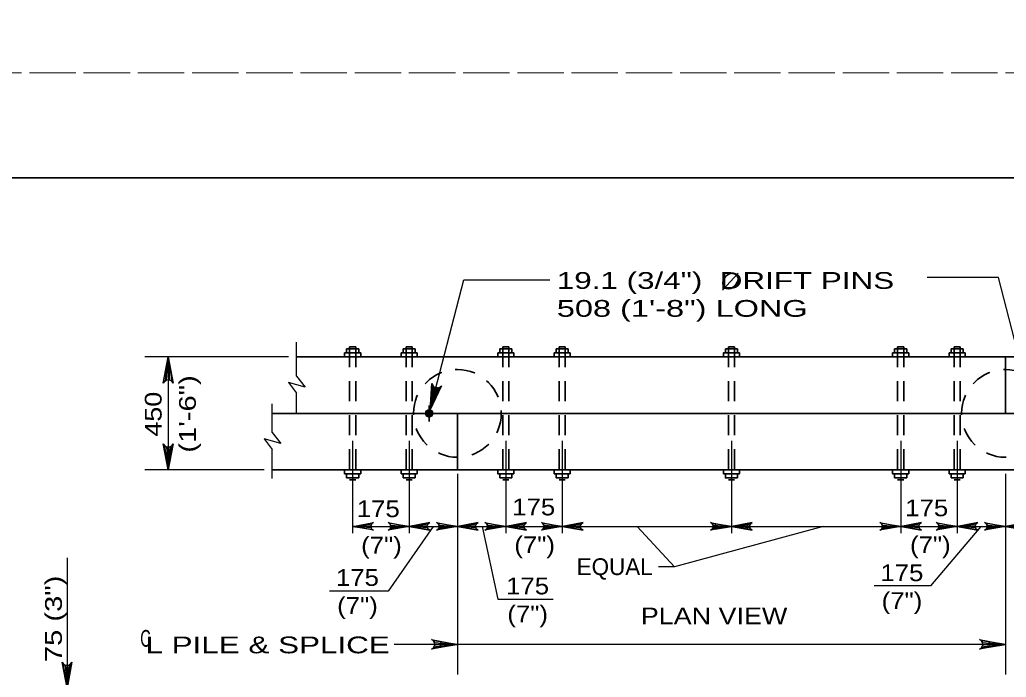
# Model space of a CAD drawing. Extents: x -6.4 to 73.1, y -66 to 0.
# Drawn here: x 22.39 to 29.45, y -26.33 to -21.62 of the extents above; entities that cross this region are included whole.
import ezdxf
from ezdxf.enums import TextEntityAlignment as Align

# ---------------------------------------------------------------- set-up
doc = ezdxf.new("R2010")
doc.units = 0
doc.header["$LTSCALE"] = 0.048
doc.linetypes.add('LONG_DASHED', pattern=[7.5, 6, -1.5])
doc.linetypes.add('MEDIUM_DASHED', pattern=[4.5, 3, -1.5])
for name, color, linetype, lineweight in [('1', 7, 'Continuous', 13), ('4', 7, 'Continuous', 25), ('5', 7, 'Continuous', 25), ('52', 7, 'Continuous', 25), ('63', 7, 'LONG_DASHED', 13)]:
    doc.layers.add(name, color=color, linetype=linetype, lineweight=lineweight)

msp = doc.modelspace()

# ---------------------------------------------------------------- hatches: boundary and pattern name
at = {"layer": '5'}
for points in [[(23.43483, -24.14433), (23.47175, -24.14433), (23.45325, -24.03358)], [(23.43483, -24.73025), (23.47175, -24.73025), (23.45325, -24.841)], [(27.36842, -25.22717), (27.36842, -25.26558), (27.48375, -25.24633)], [(27.59908, -25.26558), (27.59908, -25.22717), (27.48375, -25.24633)], [(25.40275, -26.07175), (25.40275, -26.11025), (25.51817, -26.091)], [(29.32925, -26.07175), (29.32925, -26.11025), (29.44458, -26.091)]]:
    msp.add_hatch(color=256, dxfattribs=at).paths.add_polyline_path(points)

# ---------------------------------------------------------------- linework, layer by layer
at = {"layer": '1', "lineweight": 35}
msp.add_lwpolyline([(1.75, -43.25), (33.25, -43.25), (33.25, -22.75), (1.75, -22.75)], close=True, dxfattribs=at)
at = {"layer": '4'}
for p, q in [((24.371, -24.17142), (24.371, -23.92742)), ((24.371, -24.43733), (24.371, -24.29217)), ((24.1965, -24.57508), (24.1965, -24.37)), ((24.14067, -24.61925), (24.1965, -24.69583)), ((24.25992, -24.653), (24.14067, -24.61925)), ((24.1965, -24.57508), (24.25992, -24.653)), ((24.1965, -24.90425), (24.1965, -24.69583))]:
    msp.add_line(p, q, dxfattribs=at)
at = {"layer": '4', "lineweight": 35}
for p, q in [((24.73, -24.00475), (24.73, -23.97592)), ((24.73, -23.97592), (24.8165, -23.97592)), ((24.75158, -23.9615), (24.79483, -23.9615)), ((24.8165, -24.00475), (24.8165, -23.97592)), ((25.13367, -24.00475), (25.13367, -23.97592)), ((25.13367, -23.97592), (25.22017, -23.97592)), ((25.15533, -23.9615), (25.19858, -23.9615)), ((25.22017, -24.00475), (25.22017, -23.97592)), ((25.84733, -23.9615), (25.89058, -23.9615)), ((25.91225, -24.00475), (25.91225, -23.97592)), ((26.22942, -23.97592), (26.31592, -23.97592)), ((26.22942, -24.00475), (26.22942, -23.97592)), ((26.25108, -23.9615), (26.29433, -23.9615)), ((26.31592, -24.00475), (26.31592, -23.97592)), ((27.4405, -24.00475), (27.4405, -23.97592)), ((27.4405, -23.97592), (27.527, -23.97592)), ((27.46217, -23.9615), (27.50542, -23.9615)), ((27.527, -24.00475), (27.527, -23.97592)), ((28.65158, -23.97592), (28.73808, -23.97592)), ((28.65158, -24.00475), (28.65158, -23.97592)), ((28.67325, -23.9615), (28.7165, -23.9615)), ((28.73808, -24.00475), (28.73808, -23.97592)), ((29.05525, -24.00475), (29.05525, -23.97592)), ((29.05525, -23.97592), (29.14175, -23.97592)), ((29.07692, -23.9615), (29.12017, -23.9615)), ((29.14175, -24.00475), (29.14175, -23.97592)), ((30.59658, -24.03358), (24.371, -24.03358)), ((24.71558, -24.03358), (24.71558, -24.00475)), ((24.71558, -24.00475), (24.83092, -24.00475)), ((24.83092, -24.03358), (24.83092, -24.00475)), ((25.11925, -24.03358), (25.11925, -24.00475)), ((25.11925, -24.00475), (25.23458, -24.00475)), ((25.23458, -24.03358), (25.23458, -24.00475)), ((25.81133, -24.03358), (25.81133, -24.00475)), ((25.81133, -24.00475), (25.92667, -24.00475)), ((25.92667, -24.03358), (25.92667, -24.00475)), ((26.215, -24.00475), (26.33033, -24.00475)), ((26.215, -24.03358), (26.215, -24.00475)), ((26.33033, -24.03358), (26.33033, -24.00475)), ((27.54142, -24.03358), (27.54142, -24.00475)), ((28.63717, -24.00475), (28.7525, -24.00475)), ((28.63717, -24.03358), (28.63717, -24.00475)), ((28.7525, -24.03358), (28.7525, -24.00475)), ((29.04083, -24.03358), (29.04083, -24.00475)), ((29.04083, -24.00475), (29.15625, -24.00475)), ((29.15625, -24.03358), (29.15625, -24.00475)), ((29.44458, -24.03358), (29.44458, -24.43733)), ((25.32108, -24.37967), (25.32108, -24.495)), ((30.771, -24.43733), (24.1965, -24.43733)), ((25.26342, -24.43733), (25.37875, -24.43733)), ((25.52292, -24.43733), (25.52292, -24.841)), ((30.771, -24.841), (24.1965, -24.841)), ((24.71558, -24.841), (24.71558, -24.86983)), ((24.83092, -24.841), (24.83092, -24.86983)), ((25.11925, -24.841), (25.11925, -24.86983)), ((25.23458, -24.841), (25.23458, -24.86983)), ((25.92667, -24.841), (25.92667, -24.86983)), ((26.215, -24.841), (26.215, -24.86983)), ((26.33033, -24.841), (26.33033, -24.86983)), ((27.42608, -24.841), (27.42608, -24.86983)), ((27.54142, -24.841), (27.54142, -24.86983)), ((28.63717, -24.841), (28.63717, -24.86983)), ((28.7525, -24.841), (28.7525, -24.86983)), ((29.04083, -24.841), (29.04083, -24.86983)), ((29.15625, -24.841), (29.15625, -24.86983)), ((24.71558, -24.86983), (24.83092, -24.86983)), ((24.73, -24.86983), (24.73, -24.89867)), ((24.73, -24.89867), (24.8165, -24.89867)), ((24.75158, -24.91308), (24.79483, -24.91308)), ((24.8165, -24.86983), (24.8165, -24.89867)), ((25.11925, -24.86983), (25.23458, -24.86983)), ((25.13367, -24.86983), (25.13367, -24.89867)), ((25.13367, -24.89867), (25.22017, -24.89867)), ((25.15533, -24.91308), (25.19858, -24.91308)), ((25.22017, -24.86983), (25.22017, -24.89867)), ((25.82575, -24.86983), (25.82575, -24.89867)), ((25.82575, -24.89867), (25.91225, -24.89867)), ((25.84733, -24.91308), (25.89058, -24.91308)), ((25.91225, -24.86983), (25.91225, -24.89867)), ((26.215, -24.86983), (26.33033, -24.86983)), ((26.22942, -24.86983), (26.22942, -24.89867)), ((26.22942, -24.89867), (26.31592, -24.89867)), ((26.25108, -24.91308), (26.29433, -24.91308)), ((26.31592, -24.86983), (26.31592, -24.89867)), ((27.42608, -24.86983), (27.54142, -24.86983)), ((27.46217, -24.91308), (27.50542, -24.91308)), ((27.527, -24.86983), (27.527, -24.89867)), ((28.63717, -24.86983), (28.7525, -24.86983)), ((28.65158, -24.86983), (28.65158, -24.89867)), ((28.65158, -24.89867), (28.73808, -24.89867)), ((28.67325, -24.91308), (28.7165, -24.91308)), ((28.73808, -24.86983), (28.73808, -24.89867)), ((29.04083, -24.86983), (29.15625, -24.86983)), ((29.05525, -24.86983), (29.05525, -24.89867)), ((29.05525, -24.89867), (29.14175, -24.89867)), ((29.07692, -24.91308), (29.12017, -24.91308)), ((29.14175, -24.86983), (29.14175, -24.89867))]:
    msp.add_line(p, q, dxfattribs=at)
at = {"layer": '4', "linetype": 'MEDIUM_DASHED', "lineweight": 35}
for p, q in [((24.75158, -23.9615), (24.75158, -24.91308)), ((24.79483, -23.9615), (24.79483, -24.91308)), ((25.15533, -23.9615), (25.15533, -24.91308)), ((25.19858, -23.9615), (25.19858, -24.91308)), ((25.84733, -23.9615), (25.84733, -24.91308)), ((25.89058, -23.9615), (25.89058, -24.91308)), ((26.25108, -23.9615), (26.25108, -24.91308)), ((26.29433, -23.9615), (26.29433, -24.91308)), ((27.46217, -23.9615), (27.46217, -24.91308)), ((27.50542, -23.9615), (27.50542, -24.91308)), ((28.67325, -23.9615), (28.67325, -24.91308)), ((28.7165, -23.9615), (28.7165, -24.91308)), ((29.07692, -23.9615), (29.07692, -24.91308)), ((29.12017, -23.9615), (29.12017, -24.91308))]:
    msp.add_line(p, q, dxfattribs=at)
at = {"layer": '4', "lineweight": 35}
for points in [[(25.82575, -24.00475), (25.82575, -23.97592), (25.91225, -23.97592)], [(27.42608, -24.03358), (27.42608, -24.00475), (27.54142, -24.00475)], [(25.81133, -24.841), (25.81133, -24.86983), (25.92667, -24.86983)], [(27.4405, -24.86983), (27.4405, -24.89867), (27.527, -24.89867)]]:
    msp.add_lwpolyline(points, dxfattribs=at)
at = {"layer": '4'}
msp.add_lwpolyline([(24.371, -24.17142), (24.43433, -24.24933), (24.31508, -24.21558), (24.371, -24.29217)], dxfattribs=at)
at = {"layer": '4', "linetype": 'MEDIUM_DASHED', "lineweight": 35}
for centre in [(25.52289, -24.4373), (29.44452, -24.43733)]:
    msp.add_circle(centre, 0.31393, dxfattribs=at)
at = {"layer": '5', "lineweight": 35}
msp.add_line((27.419, -23.55508), (27.531, -23.4325), dxfattribs=at)
at = {"layer": '5'}
for p, q in [((24.31333, -24.03358), (23.28717, -24.03358)), ((23.45325, -24.03358), (23.45325, -24.841)), ((24.77325, -24.63433), (24.77325, -25.29592)), ((25.17692, -24.63433), (25.17692, -25.29592)), ((25.869, -24.63433), (25.869, -25.29592)), ((26.27267, -24.63433), (26.27267, -25.29592)), ((27.48375, -24.63433), (27.48375, -25.29592)), ((28.69483, -24.63433), (28.69483, -25.29592)), ((29.0985, -24.63433), (29.0985, -25.29592)), ((24.13883, -24.841), (23.28717, -24.841)), ((25.52292, -24.86983), (25.52292, -26.30625)), ((29.44458, -24.86983), (29.44458, -26.30625)), ((24.77325, -25.24633), (27.48375, -25.24633)), ((26.81008, -25.24633), (27.07575, -25.53483)), ((27.48375, -25.24633), (30.19425, -25.24633)), ((22.7295, -25.47083), (22.7295, -26.57733)), ((29.44458, -26.091), (25.071, -26.091))]:
    msp.add_line(p, q, dxfattribs=at)
for points in [[(25.32767, -24.4115), (25.56917, -23.48108), (26.18492, -23.48108)], [(29.64075, -24.41575), (29.39475, -23.46383), (28.88358, -23.46383)], [(23.45325, -24.03358), (23.48817, -24.22), (23.47825, -24.20567), (23.46575, -24.19825), (23.45325, -24.19608), (23.44075, -24.19825), (23.42825, -24.20567), (23.41833, -24.22), (23.45325, -24.03358), (23.42825, -24.20567), (23.44075, -24.19825), (23.45325, -24.03358), (23.45325, -24.19608), (23.46575, -24.19825), (23.45325, -24.03358), (23.47825, -24.20567)], [(25.32767, -24.4115), (25.34067, -24.22225), (25.34367, -24.2305), (25.34667, -24.23867), (25.35183, -24.24383), (25.35692, -24.249), (25.36267, -24.25158), (25.3685, -24.25417), (25.37483, -24.25475), (25.38108, -24.25525), (25.38808, -24.25325), (25.39508, -24.25125), (25.40167, -24.2455), (25.40833, -24.23983), (25.32767, -24.4115), (25.40167, -24.2455), (25.39508, -24.25125), (25.32767, -24.4115), (25.38808, -24.25325), (25.38108, -24.25525), (25.32767, -24.4115), (25.37483, -24.25475), (25.3685, -24.25417), (25.32767, -24.4115), (25.36267, -24.25158), (25.35692, -24.249), (25.32767, -24.4115), (25.35183, -24.24383), (25.34667, -24.23867), (25.32767, -24.4115), (25.34367, -24.2305)], [(23.45325, -24.841), (23.41833, -24.65458), (23.42825, -24.66892), (23.44075, -24.67633), (23.45325, -24.6785), (23.46575, -24.67633), (23.47825, -24.66892), (23.48817, -24.65458), (23.45325, -24.841), (23.47825, -24.66892), (23.46575, -24.67633), (23.45325, -24.841), (23.45325, -24.6785), (23.44075, -24.67633), (23.45325, -24.841), (23.42825, -24.66892)], [(24.77325, -25.24633), (24.92242, -25.21833), (24.91092, -25.22633), (24.905, -25.23633), (24.90325, -25.24633), (24.905, -25.25633), (24.91092, -25.26633), (24.92242, -25.27433), (24.77325, -25.24633), (24.91092, -25.26633), (24.905, -25.25633), (24.77325, -25.24633), (24.90325, -25.24633), (24.905, -25.23633), (24.77325, -25.24633), (24.91092, -25.22633)], [(25.17692, -25.24633), (25.02775, -25.27433), (25.03925, -25.26633), (25.04517, -25.25633), (25.04692, -25.24633), (25.04517, -25.23633), (25.03925, -25.22633), (25.02775, -25.21833), (25.17692, -25.24633), (25.03925, -25.22633), (25.04517, -25.23633), (25.17692, -25.24633), (25.04692, -25.24633), (25.04517, -25.25633), (25.17692, -25.24633), (25.03925, -25.26633)], [(25.17692, -25.24633), (25.32608, -25.27433), (25.31458, -25.26633), (25.30867, -25.25633), (25.30692, -25.24633), (25.30867, -25.23633), (25.31458, -25.22633), (25.32608, -25.21833), (25.17692, -25.24633), (25.31458, -25.22633), (25.30867, -25.23633), (25.17692, -25.24633), (25.30692, -25.24633), (25.30867, -25.25633), (25.17692, -25.24633), (25.31458, -25.26633)], [(25.52292, -25.24633), (25.37375, -25.27433), (25.38525, -25.26633), (25.39117, -25.25633), (25.39292, -25.24633), (25.39117, -25.23633), (25.38525, -25.22633), (25.37375, -25.21833), (25.52292, -25.24633), (25.38525, -25.22633), (25.39117, -25.23633), (25.52292, -25.24633), (25.39292, -25.24633), (25.39117, -25.25633), (25.52292, -25.24633), (25.38525, -25.26633)], [(25.52292, -25.24633), (25.67208, -25.27433), (25.66058, -25.26633), (25.65467, -25.25633), (25.65292, -25.24633), (25.65467, -25.23633), (25.66058, -25.22633), (25.67208, -25.21833), (25.52292, -25.24633), (25.66058, -25.22633), (25.65467, -25.23633), (25.52292, -25.24633), (25.65292, -25.24633), (25.65467, -25.25633), (25.52292, -25.24633), (25.66058, -25.26633)], [(25.869, -25.24633), (25.71983, -25.27433), (25.73133, -25.26633), (25.73725, -25.25633), (25.739, -25.24633), (25.73725, -25.23633), (25.73133, -25.22633), (25.71983, -25.21833), (25.869, -25.24633), (25.73133, -25.22633), (25.73725, -25.23633), (25.869, -25.24633), (25.739, -25.24633), (25.73725, -25.25633), (25.869, -25.24633), (25.73133, -25.26633)], [(25.869, -25.24633), (26.01817, -25.27433), (26.00667, -25.26633), (26.00075, -25.25633), (25.999, -25.24633), (26.00075, -25.23633), (26.00667, -25.22633), (26.01817, -25.21833), (25.869, -25.24633), (26.00667, -25.22633), (26.00075, -25.23633), (25.869, -25.24633), (25.999, -25.24633), (26.00075, -25.25633), (25.869, -25.24633), (26.00667, -25.26633)], [(26.27267, -25.24633), (26.1235, -25.27433), (26.135, -25.26633), (26.14092, -25.25633), (26.14267, -25.24633), (26.14092, -25.23633), (26.135, -25.22633), (26.1235, -25.21833), (26.27267, -25.24633), (26.135, -25.22633), (26.14092, -25.23633), (26.27267, -25.24633), (26.14267, -25.24633), (26.14092, -25.25633), (26.27267, -25.24633), (26.135, -25.26633)], [(26.27267, -25.24633), (26.42183, -25.27433), (26.41033, -25.26633), (26.40442, -25.25633), (26.40267, -25.24633), (26.40442, -25.23633), (26.41033, -25.22633), (26.42183, -25.21833), (26.27267, -25.24633), (26.41033, -25.22633), (26.40442, -25.23633), (26.27267, -25.24633), (26.40267, -25.24633), (26.40442, -25.25633), (26.27267, -25.24633), (26.41033, -25.26633)], [(28.1405, -25.24633), (27.07575, -25.53483), (26.96225, -25.53483)], [(27.48375, -25.24633), (27.33458, -25.27433), (27.34608, -25.26633), (27.352, -25.25633), (27.35375, -25.24633), (27.352, -25.23633), (27.34608, -25.22633), (27.33458, -25.21833), (27.48375, -25.24633), (27.34608, -25.22633), (27.352, -25.23633), (27.48375, -25.24633), (27.35375, -25.24633), (27.352, -25.25633), (27.48375, -25.24633), (27.34608, -25.26633)], [(27.48375, -25.24633), (27.63292, -25.27433), (27.62142, -25.26633), (27.6155, -25.25633), (27.61375, -25.24633), (27.6155, -25.23633), (27.62142, -25.22633), (27.63292, -25.21833), (27.48375, -25.24633), (27.62142, -25.22633), (27.6155, -25.23633), (27.48375, -25.24633), (27.61375, -25.24633), (27.6155, -25.25633), (27.48375, -25.24633), (27.62142, -25.26633)], [(28.69483, -25.24633), (28.54567, -25.27433), (28.55717, -25.26633), (28.56308, -25.25633), (28.56483, -25.24633), (28.56308, -25.23633), (28.55717, -25.22633), (28.54567, -25.21833), (28.69483, -25.24633), (28.55717, -25.22633), (28.56308, -25.23633), (28.69483, -25.24633), (28.56483, -25.24633), (28.56308, -25.25633), (28.69483, -25.24633), (28.55717, -25.26633)], [(28.69483, -25.24633), (28.844, -25.27433), (28.8325, -25.26633), (28.82658, -25.25633), (28.82483, -25.24633), (28.82658, -25.23633), (28.8325, -25.22633), (28.844, -25.21833), (28.69483, -25.24633), (28.8325, -25.22633), (28.82658, -25.23633), (28.69483, -25.24633), (28.82483, -25.24633), (28.82658, -25.25633), (28.69483, -25.24633), (28.8325, -25.26633)], [(29.0985, -25.24633), (28.94933, -25.27433), (28.96083, -25.26633), (28.96675, -25.25633), (28.9685, -25.24633), (28.96675, -25.23633), (28.96083, -25.22633), (28.94933, -25.21833), (29.0985, -25.24633), (28.96083, -25.22633), (28.96675, -25.23633), (29.0985, -25.24633), (28.9685, -25.24633), (28.96675, -25.25633), (29.0985, -25.24633), (28.96083, -25.26633)], [(29.0985, -25.24633), (29.24767, -25.27433), (29.23617, -25.26633), (29.23025, -25.25633), (29.2285, -25.24633), (29.23025, -25.23633), (29.23617, -25.22633), (29.24767, -25.21833), (29.0985, -25.24633), (29.23617, -25.22633), (29.23025, -25.23633), (29.0985, -25.24633), (29.2285, -25.24633), (29.23025, -25.25633), (29.0985, -25.24633), (29.23617, -25.26633)], [(29.44458, -25.24633), (29.29542, -25.27433), (29.30692, -25.26633), (29.31283, -25.25633), (29.31458, -25.24633), (29.31283, -25.23633), (29.30692, -25.22633), (29.29542, -25.21833), (29.44458, -25.24633), (29.30692, -25.22633), (29.31283, -25.23633), (29.44458, -25.24633), (29.31458, -25.24633), (29.31283, -25.25633), (29.44458, -25.24633), (29.30692, -25.26633)], [(29.44458, -25.24633), (29.59375, -25.27433), (29.58225, -25.26633), (29.57633, -25.25633), (29.57458, -25.24633), (29.57633, -25.23633), (29.58225, -25.22633), (29.59375, -25.21833), (29.44458, -25.24633), (29.58225, -25.22633), (29.57633, -25.23633), (29.44458, -25.24633), (29.57458, -25.24633), (29.57633, -25.25633), (29.44458, -25.24633), (29.58225, -25.26633)], [(25.52292, -26.091), (25.3365, -26.12592), (25.35083, -26.116), (25.35825, -26.1035), (25.36042, -26.091), (25.35825, -26.0785), (25.35083, -26.066), (25.3365, -26.05608), (25.52292, -26.091), (25.35083, -26.066), (25.35825, -26.0785), (25.52292, -26.091), (25.36042, -26.091), (25.35825, -26.1035), (25.52292, -26.091), (25.35083, -26.116)], [(29.44458, -26.091), (29.25817, -26.12592), (29.2725, -26.116), (29.27992, -26.1035), (29.28208, -26.091), (29.27992, -26.0785), (29.2725, -26.066), (29.25817, -26.05608), (29.44458, -26.091), (29.2725, -26.066), (29.27992, -26.0785), (29.44458, -26.091), (29.28208, -26.091), (29.27992, -26.1035), (29.44458, -26.091), (29.2725, -26.116)], [(22.7295, -26.40433), (22.69458, -26.21792), (22.7045, -26.23225), (22.717, -26.23967), (22.7295, -26.24183), (22.742, -26.23967), (22.7545, -26.23225), (22.76442, -26.21792), (22.7295, -26.40433), (22.7545, -26.23225), (22.742, -26.23967), (22.7295, -26.40433), (22.7295, -26.24183), (22.717, -26.23967), (22.7295, -26.40433), (22.7045, -26.23225)]]:
    msp.add_lwpolyline(points, dxfattribs=at)
for points in [[(23.43483, -24.14433), (23.47175, -24.14433), (23.45325, -24.03358)], [(23.43483, -24.73025), (23.47175, -24.73025), (23.45325, -24.841)], [(27.36842, -25.22717), (27.36842, -25.26558), (27.48375, -25.24633)], [(27.59908, -25.26558), (27.59908, -25.22717), (27.48375, -25.24633)], [(25.40275, -26.07175), (25.40275, -26.11025), (25.51817, -26.091)], [(29.32925, -26.07175), (29.32925, -26.11025), (29.44458, -26.091)]]:
    msp.add_lwpolyline(points, close=True, dxfattribs=at)
for radius in [0.02667, 0.02, 0.01333, 0.00667]:
    msp.add_circle((25.32102, -24.43733), radius, dxfattribs=at)
at = {"layer": '5', "lineweight": 35}
msp.add_spline([(27.51933, -23.44458), (27.51058, -23.43775), (27.50183, -23.43533), (27.49083, -23.43433), (27.48458, -23.43433), (27.47383, -23.43683), (27.464, -23.44133), (27.45708, -23.44525), (27.44383, -23.45583), (27.4335, -23.46933), (27.42725, -23.482), (27.42358, -23.49358), (27.4225, -23.50433), (27.42358, -23.51358), (27.42808, -23.52675), (27.43283, -23.53358), (27.4425, -23.54083), (27.457, -23.54433), (27.4735, -23.54383), (27.49433, -23.53433), (27.50958, -23.52125), (27.52108, -23.50533), (27.52858, -23.48875), (27.53108, -23.47033), (27.52783, -23.4585), (27.51983, -23.44458)], degree=3, dxfattribs=at)
at = {"layer": '52'}
for points in [[(25.34933, -25.24633), (25.02775, -25.7105), (24.60783, -25.7105)], [(25.69975, -25.24633), (25.8125, -25.76817), (26.2085, -25.76817)], [(29.26808, -25.24633), (28.90908, -25.673), (28.50408, -25.673)]]:
    msp.add_lwpolyline(points, dxfattribs=at)
at = {"layer": '63'}
for points in [[(0, -22), (34, -22), (34, 0), (0, 0)], [(0, -44), (34, -44), (34, -22), (0, -22)]]:
    msp.add_lwpolyline(points, close=True, dxfattribs=at)

# ---------------------------------------------------------------- texts
at = {"layer": '5'}
for s, width, p in [('19.1 (3/4")  DRIFT PINS', 1.4, (26.23408, -23.54567)), ('508 (1\'-8") LONG', 1.45, (26.23408, -23.74567)), ('C', 0.65, (23.25333, -26.10792)), ('L PILE & SPLICE', 1.4, (23.29067, -26.15483))]:
    msp.add_text(s, height=0.12, dxfattribs=dict(at, width=width)).set_placement(p)
for s, width, p in [('(1\'-6")', 1.3, (23.65117, -24.44125)), ('450', 1.2, (23.40625, -24.44312))]:
    msp.add_text(s, height=0.12, rotation=90, dxfattribs=dict(at, width=width)).set_placement(p, align=Align.CENTER)
for s, width, p in [('175', 1.15, (24.9565, -25.18017)), ('175', 1.15, (26.06867, -25.16742)), ('175', 1.15, (28.88117, -25.17383)), ('(7")', 1.15, (24.97942, -25.441)), ('(7")', 1.15, (26.07558, -25.43783)), ('(7")', 1.15, (28.90725, -25.43783)), ('175', 1.15, (24.80733, -25.67242)), ('175', 1.15, (28.70358, -25.63825)), ('175', 1.15, (26.02508, -25.73283)), ('(7")', 1.15, (24.80783, -25.87242)), ('(7")', 1.15, (28.70408, -25.83825)), ('(7")', 1.15, (26.02558, -25.93283)), ('PLAN VIEW', 1.2, (27.35946, -25.9475))]:
    msp.add_text(s, height=0.12, dxfattribs=dict(at, width=width)).set_placement(p, align=Align.CENTER)
msp.add_text('EQUAL', height=0.12, dxfattribs=at).set_placement((26.64817, -25.59475), align=Align.CENTER)
at = {"layer": '5', "width": 1.3}
msp.add_text('75 (3")', height=0.12, rotation=90, dxfattribs=at).set_placement((22.69233, -26.21792))

doc.saveas('drawing.dxf')
